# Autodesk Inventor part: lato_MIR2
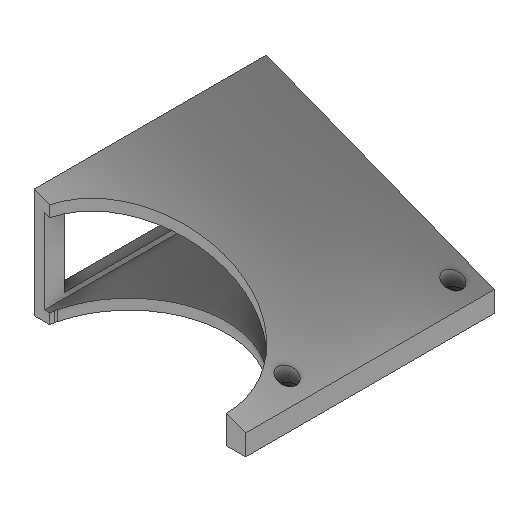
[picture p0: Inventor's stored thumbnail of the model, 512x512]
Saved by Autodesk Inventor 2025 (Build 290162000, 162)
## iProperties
Created: 2025-05
Part Number: lato_MIR2
Material: Plastica PET
Document SubType Name: Modeling
Designer: R5800u
Density: 1.541 g/cm^3
Appearance: Policarbonato - Trasparente
Author: R5800u
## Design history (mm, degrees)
derived "lato.ipt"
  sketch "Schizzo1"
    geometry: L1 (0, 0)-(-190, 0) reference; L2 (-190, 0)-(-190, 5) reference; L3 (0, 5)-(-190, 5) reference; L4 (0, 0)-(0, 5) reference; L5 (-300, -48)-(-300, -53) reference; L6 (-300, -48)-(-300, -38) reference; L7 (-300, -38)-(-190, 5) reference; L8 (-190, 5)-(-190, -48) reference; L9 (-190, -48)-(-300, -48) reference; L10 (-195, -2.323)-(-295, -41.414) reference; L11 (-295, -41.414)-(-295, -43) reference; L12 (-295, -43)-(-195, -43) reference; L13 (-195, -43)-(-195, -2.323) reference; L14 (-284, -37.114)-(-284, -43) reference
  sketch "Schizzo2"
    geometry: L1 (0, 53)-(0, 0) reference; L2 (0, 53)-(120, 53) reference; L3 (120, 0)-(120, 53) reference; L4 (0, 0)-(120, 0) reference; L5 (112.5, 45.5)-(7.5, 45.5) reference; L6 (7.5, 45.5)-(7.5, 7.5) reference; L7 (7.5, 7.5)-(112.5, 7.5) reference; L8 (112.5, 7.5)-(112.5, 45.5) reference; L9 (102.5, 45.5)-(102.5, 43.336) reference; L10 (102.5, 43.336)-(102.5, 7.5) reference; 1 further point
  sketch "Schizzo3"
    geometry: L1 (-81.5, -69.5)-(-81.5, -61.5) reference; L2 (-93.5, -69.5)-(-81.5, -69.5) reference; L3 (-93.5, -61.5)-(-93.5, -69.5) reference; L4 (-81.5, -61.5)-(-93.5, -61.5) reference; L5 (-93.5, 61.5)-(-81.5, 61.5) reference; L6 (-81.5, 61.5)-(-81.5, 69.5) reference; L7 (-81.5, 69.5)-(-93.5, 69.5) reference; 1 further point
  sketch "Schizzo4"
    geometry: L1 (0, -120)-(-110, -120) reference; L2 (-100, -120)-(-100, 0) reference; L3 (0, 0)-(-110, 0) reference; L4 (-100, -60)-(-110, -60) reference; L5 (-110, 0)-(-110, -120) reference; L6 (-100, -10)-(-10, -10) reference; L7 (0, 0)-(0, -120) reference; 6 further points
  node "Piano di lavoro1"
  node "Piano di lavoro2"
feature "Solido1::lato.ipt"
tag "Lavorazione contrassegno1"
sketch "Schizzo6"
  geometry: C1 r 2.25 at (-95, 90) reference; C2 r 2.25 at (-95, 10) reference; 1 further point
sketch "Schizzo8"
  geometry: L1 (0, -148.74)-(0, -92.562) reference; L2 (0, -148.74)-(0, -200.951) reference; L3 (0, -205)-(0, -95) reference; L4 (8, -102.426)-(8, -95) reference; L5 (120, -95)-(0, -95) reference; A1 r 45 centre (0, -148.74) between (-0.743, -193.734) and (-0.743, -103.747) reference; A2 r 47 centre (0, -148.74) between (-0.776, -195.734) and (-0.776, -101.747) reference; 1 further point
node "Solido1"
